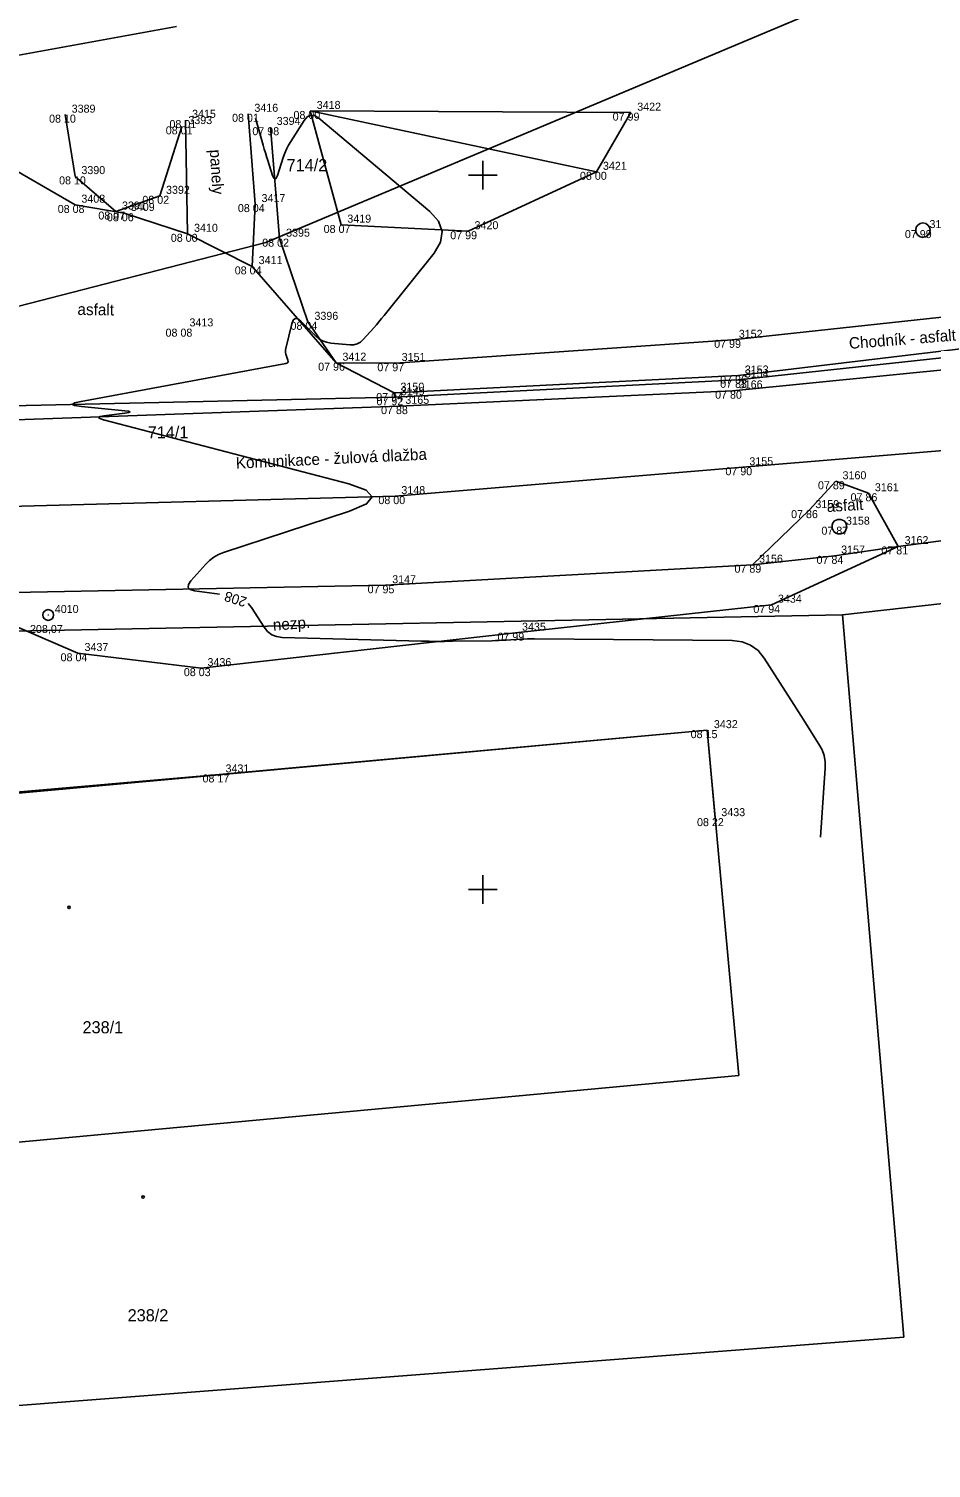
# Model space of a CAD drawing. Extents: x -703403 to -701924, y -1022520 to -1021856.
# Drawn here: x -702540.9 to -702509.3, y -1022370.2 to -1022319.9 of the extents above; entities that cross this region are included whole.
import ezdxf

# ---------------------------------------------------------------- set-up
doc = ezdxf.new("R2010")
doc.units = 0
for name, color, linetype in [('Ex_Contour Labels', 7, 'Continuous'), ('Ex_Major Contours', 7, 'Continuous'), ('Z_bodove_pole', 7, 'Continuous'), ('Z_bodove_pole_cisla', 7, 'Continuous'), ('Z_bodove_pole_vysky', 7, 'Continuous'), ('Z_body', 7, 'Continuous'), ('Z_body_cisla', 7, 'Continuous'), ('Z_body_vysky_redukovane', 7, 'Continuous'), ('Z_budova', 7, 'Continuous'), ('Z_cesta', 7, 'Continuous'), ('Z_chodnik', 7, 'Continuous'), ('Z_hektometricka_sit', 7, 'Continuous'), ('Z_katastr_cisla_pozemkova', 7, 'Continuous'), ('Z_katastr_cisla_stavebni', 7, 'Continuous'), ('Z_katastr_hranice', 7, 'Continuous'), ('Z_katastr_znacky_budov', 7, 'Continuous'), ('Z_komunikace', 7, 'Continuous'), ('Z_komunikace_osa', 7, 'Continuous'), ('Z_obruba', 7, 'Continuous'), ('Z_popisy', 7, 'Continuous'), ('Z_rozhranni', 7, 'Continuous'), ('Z_site_kanalizace_znaky', 7, 'Continuous'), ('Z_zelen_jednotliva', 7, 'Continuous'), ('Z_zelen_obvod', 7, 'Continuous')]:
    doc.layers.add(name, color=color, linetype=linetype)

# ---------------------------------------------------------------- blocks, each defined once
blk = doc.blocks.new('POINT_DISPLAY')
blk.add_line((0, 0), (0, 0))
blk = doc.blocks.new('Z10001')
blk.add_circle((0, 0), 0.25)
blk = doc.blocks.new('Z620')
for p, q in [((-0.25, 0.05), (-0.23, 0.13)), ((-0.25, -0.05), (-0.25, 0.05)), ((-0.23, 0.13), (-0.17, 0.2)), ((-0.17, 0.2), (-0.05, 0.25)), ((-0.05, 0.25), (0.05, 0.25)), ((0.05, 0.25), (0.17, 0.2)), ((0.17, 0.2), (0.23, 0.13)), ((0.23, 0.13), (0.25, 0.05)), ((0.25, 0.05), (0.25, -0.05)), ((-0.2, -0.17), (-0.25, -0.05)), ((-0.13, -0.23), (-0.2, -0.17)), ((-0.05, -0.25), (-0.13, -0.23)), ((0.05, -0.25), (-0.05, -0.25)), ((0.13, -0.23), (0.05, -0.25)), ((0.2, -0.17), (0.13, -0.23)), ((0.25, -0.05), (0.2, -0.17))]:
    blk.add_line(p, q)
blk = doc.blocks.new('Z101')
for radius in [0.188, 0.0025]:
    blk.add_circle((0, 0), radius)

msp = doc.modelspace()

# ---------------------------------------------------------------- linework, layer by layer
at = {"layer": 'Ex_Major Contours'}
for points in [[(-702531.04, -1022322.75), (-702521.02, -1022324.88)], [(-702534.21, -1022339.66), (-702535.084, -1022339.539), (-702535.236, -1022339.498), (-702535.307, -1022339.427), (-702535.299, -1022339.327), (-702535.21, -1022339.197), (-702534.693, -1022338.617), (-702534.557, -1022338.482), (-702534.407, -1022338.369), (-702534.243, -1022338.277), (-702534.066, -1022338.205), (-702529.661, -1022336.754), (-702529.066, -1022336.498), (-702528.873, -1022336.255), (-702529.081, -1022336.024), (-702529.691, -1022335.805), (-702538.261, -1022333.56), (-702538.394, -1022333.516), (-702538.437, -1022333.478), (-702538.389, -1022333.446), (-702538.252, -1022333.42), (-702537.523, -1022333.326), (-702537.386, -1022333.303), (-702537.341, -1022333.281), (-702537.387, -1022333.261), (-702537.524, -1022333.243), (-702539.041, -1022333.094), (-702539.277, -1022333.059), (-702539.356, -1022333.018), (-702539.28, -1022332.971), (-702539.048, -1022332.917), (-702531.895, -1022331.589), (-702531.851, -1022331.575), (-702531.824, -1022331.549), (-702531.814, -1022331.514), (-702531.822, -1022331.468), (-702531.885, -1022331.265), (-702531.897, -1022331.214), (-702531.902, -1022331.163), (-702531.9, -1022331.112), (-702531.891, -1022331.06), (-702531.679, -1022330.197), (-702531.63, -1022330.071), (-702531.561, -1022330.014), (-702531.473, -1022330.027), (-702531.365, -1022330.109), (-702530.848, -1022330.623), (-702530.731, -1022330.722), (-702530.602, -1022330.797), (-702530.463, -1022330.847), (-702530.312, -1022330.873), (-702529.649, -1022330.933), (-702529.516, -1022330.931), (-702529.394, -1022330.9), (-702529.284, -1022330.84), (-702529.186, -1022330.751), (-702528.815, -1022330.336), (-702528.723, -1022330.231), (-702528.633, -1022330.126), (-702528.544, -1022330.019), (-702528.456, -1022329.911), (-702526.707, -1022327.731), (-702526.476, -1022327.341), (-702526.422, -1022326.967), (-702526.547, -1022326.612), (-702526.85, -1022326.273), (-702530.739, -1022323.003), (-702530.884, -1022322.913), (-702531.017, -1022322.896), (-702531.139, -1022322.953), (-702531.25, -1022323.083), (-702531.714, -1022323.815), (-702531.793, -1022323.95), (-702531.864, -1022324.088), (-702531.925, -1022324.231), (-702531.978, -1022324.378), (-702532.184, -1022325.007), (-702532.227, -1022325.106), (-702532.27, -1022325.138), (-702532.312, -1022325.105), (-702532.354, -1022325.007), (-702532.523, -1022324.48), (-702532.564, -1022324.348), (-702532.604, -1022324.216), (-702532.644, -1022324.084), (-702532.682, -1022323.951), (-702532.95, -1022323.007)], [(-702513.187, -1022348.164), (-702513.029, -1022345.753), (-702513.031, -1022345.529), (-702513.068, -1022345.313), (-702513.139, -1022345.106), (-702513.244, -1022344.908), (-702513.734, -1022344.134), (-702513.857, -1022343.94), (-702513.98, -1022343.747), (-702514.103, -1022343.554), (-702514.226, -1022343.361), (-702515.157, -1022341.905), (-702515.375, -1022341.636), (-702515.634, -1022341.443), (-702515.935, -1022341.326), (-702516.279, -1022341.285), (-702523.191, -1022341.225), (-702523.316, -1022341.225), (-702523.441, -1022341.228), (-702523.565, -1022341.232), (-702523.689, -1022341.239), (-702524.187, -1022341.27), (-702524.311, -1022341.277), (-702524.436, -1022341.283), (-702524.56, -1022341.287), (-702524.685, -1022341.29), (-702526.065, -1022341.311), (-702526.336, -1022341.314), (-702526.607, -1022341.314), (-702526.879, -1022341.311), (-702527.15, -1022341.305), (-702532.022, -1022341.174), (-702532.215, -1022341.147), (-702532.384, -1022341.079), (-702532.53, -1022340.969), (-702532.653, -1022340.818), (-702533.095, -1022340.128), (-702533.21, -1022339.983)]]:
    msp.add_lwpolyline(points, dxfattribs=at)
at = {"layer": 'Z_budova'}
for p, q in [((-702534.22, -1022345.97), (-702517.15, -1022344.42)), ((-702517.15, -1022344.42), (-702516.88, -1022347.5)), ((-702547.33, -1022347.12), (-702534.22, -1022345.97))]:
    msp.add_line(p, q, dxfattribs=at)
at = {"layer": 'Z_cesta'}
for p, q in [((-702539.61, -1022322.88), (-702539.26, -1022325.04)), ((-702536.3, -1022325.72), (-702535.53, -1022323.29)), ((-702532.43, -1022323.32), (-702532.11, -1022327.22)), ((-702539.26, -1022325.04), (-702537.84, -1022326.27)), ((-702537.84, -1022326.27), (-702536.3, -1022325.72)), ((-702532.11, -1022327.22), (-702531.12, -1022330.13)), ((-702531.12, -1022330.13), (-702530.13, -1022331.56))]:
    msp.add_line(p, q, dxfattribs=at)
at = {"layer": 'Z_chodnik'}
for p, q in [((-702516.28, -1022330.76), (-702504.25, -1022329.46)), ((-702528.06, -1022331.58), (-702516.28, -1022330.76)), ((-702528.06, -1022331.58), (-702530.13, -1022331.56))]:
    msp.add_line(p, q, dxfattribs=at)
at = {"layer": 'Z_hektometricka_sit'}
for p, q in [((-702525, -1022324.5), (-702525, -1022325.5)), ((-702525.5, -1022325), (-702524.5, -1022325)), ((-702525, -1022349.5), (-702525, -1022350.5)), ((-702525.5, -1022350), (-702524.5, -1022350))]:
    msp.add_line(p, q, dxfattribs=at)
at = {"layer": 'Z_katastr_hranice'}
for p, q in [((-702509.32, -1022317.56), (-702532.59, -1022327.36)), ((-702544.68, -1022321.42), (-702535.71, -1022319.8)), ((-702532.59, -1022327.36), (-702542.68, -1022329.95)), ((-702461.35, -1022334.53), (-702512.42, -1022340.39)), ((-702512.42, -1022340.39), (-702559.94, -1022341.31)), ((-702510.28, -1022365.66), (-702512.42, -1022340.39)), ((-702517.15, -1022344.42), (-702564.67, -1022348.77)), ((-702516.05, -1022356.51), (-702517.15, -1022344.42)), ((-702563.56, -1022360.91), (-702516.05, -1022356.51)), ((-702569.75, -1022370.25), (-702510.28, -1022365.66))]:
    msp.add_line(p, q, dxfattribs=at)
at = {"layer": 'Z_katastr_znacky_budov'}
for centre in [(-702539.472, -1022350.62), (-702536.882, -1022360.76)]:
    msp.add_circle(centre, 0.0437, dxfattribs=at)
at = {"layer": 'Z_komunikace'}
for p, q in [((-702542.16, -1022324.36), (-702539.26, -1022326.04)), ((-702539.26, -1022326.04), (-702537.54, -1022326.33)), ((-702537.54, -1022326.33), (-702535.33, -1022327.05)), ((-702535.33, -1022327.05), (-702533.07, -1022328.19)), ((-702533.07, -1022328.19), (-702530.13, -1022331.56)), ((-702516.07, -1022332.16), (-702504.15, -1022330.87)), ((-702530.13, -1022331.56), (-702528.1, -1022332.62)), ((-702528.09, -1022332.77), (-702516.07, -1022332.16)), ((-702528.09, -1022332.77), (-702544.01, -1022333.13)), ((-702510.48, -1022337.99), (-702504.07, -1022337.14)), ((-702515.57, -1022338.63), (-702512.7, -1022338.32)), ((-702512.7, -1022338.32), (-702510.48, -1022337.99)), ((-702528.4, -1022339.35), (-702515.57, -1022338.63)), ((-702543.95, -1022339.65), (-702528.4, -1022339.35))]:
    msp.add_line(p, q, dxfattribs=at)
at = {"layer": 'Z_komunikace_osa'}
for p, q in [((-702515.91, -1022335.22), (-702503.96, -1022334.23)), ((-702528.07, -1022336.23), (-702515.91, -1022335.22)), ((-702551.96, -1022336.87), (-702528.07, -1022336.23))]:
    msp.add_line(p, q, dxfattribs=at)
at = {"layer": 'Z_obruba'}
for p, q in [((-702516.07, -1022332.01), (-702504.2, -1022330.59)), ((-702528.1, -1022332.62), (-702516.07, -1022332.01)), ((-702528.1, -1022332.62), (-702528.09, -1022332.77))]:
    msp.add_line(p, q, dxfattribs=at)
at = {"layer": 'Z_rozhranni'}
for p, q in [((-702535.4, -1022323.07), (-702535.33, -1022327.05)), ((-702533.21, -1022322.85), (-702532.96, -1022326.01)), ((-702532.96, -1022326.01), (-702533.07, -1022328.19)), ((-702516.27, -1022332.54), (-702504.24, -1022331.34)), ((-702527.93, -1022333.08), (-702516.27, -1022332.54)), ((-702543.96, -1022333.66), (-702527.93, -1022333.08)), ((-702513.59, -1022336.72), (-702512.65, -1022335.71)), ((-702512.65, -1022335.71), (-702511.51, -1022336.13)), ((-702510.48, -1022337.99), (-702511.51, -1022336.13)), ((-702513.59, -1022336.72), (-702515.57, -1022338.63)), ((-702514.91, -1022340.04), (-702510.48, -1022337.99)), ((-702539.16, -1022341.73), (-702543.95, -1022339.65)), ((-702514.91, -1022340.04), (-702523.86, -1022341.01)), ((-702523.86, -1022341.01), (-702534.85, -1022342.25)), ((-702534.85, -1022342.25), (-702539.16, -1022341.73))]:
    msp.add_line(p, q, dxfattribs=at)
at = {"layer": 'Z_zelen_obvod'}
for p, q in [((-702531.04, -1022322.75), (-702529.96, -1022326.74)), ((-702531.04, -1022322.75), (-702519.83, -1022322.81)), ((-702521.02, -1022324.88), (-702519.83, -1022322.81)), ((-702525.51, -1022326.96), (-702521.02, -1022324.88)), ((-702529.96, -1022326.74), (-702525.51, -1022326.96))]:
    msp.add_line(p, q, dxfattribs=at)

# ---------------------------------------------------------------- block references
at = {"layer": 'Z_bodove_pole'}
msp.add_blockref('Z101', (-702540.2, -1022340.39), dxfattribs=at)
at = {"layer": 'Z_body'}
for p in [(-702531.04, -1022322.75), (-702519.83, -1022322.81), (-702539.61, -1022322.88), (-702535.53, -1022323.29), (-702535.4, -1022323.07), (-702533.21, -1022322.85), (-702532.43, -1022323.32), (-702539.26, -1022325.04), (-702521.02, -1022324.88), (-702536.3, -1022325.72), (-702539.26, -1022326.04), (-702537.84, -1022326.27), (-702537.54, -1022326.33), (-702532.96, -1022326.01), (-702529.96, -1022326.74), (-702535.33, -1022327.05), (-702532.11, -1022327.22), (-702525.51, -1022326.96), (-702509.61, -1022326.92), (-702533.07, -1022328.19), (-702535.49, -1022330.37), (-702531.12, -1022330.13), (-702516.28, -1022330.76), (-702530.13, -1022331.56), (-702528.06, -1022331.58), (-702516.07, -1022332.01), (-702516.07, -1022332.16), (-702528.1, -1022332.62), (-702528.09, -1022332.77), (-702516.27, -1022332.54), (-702527.93, -1022333.08), (-702515.91, -1022335.22), (-702512.65, -1022335.71), (-702528.07, -1022336.23), (-702511.51, -1022336.13), (-702513.59, -1022336.72), (-702512.53, -1022337.3), (-702512.7, -1022338.32), (-702510.48, -1022337.99), (-702515.57, -1022338.63), (-702528.4, -1022339.35), (-702540.2, -1022340.39), (-702514.91, -1022340.04), (-702523.86, -1022341.01), (-702539.16, -1022341.73), (-702534.85, -1022342.25), (-702517.15, -1022344.42), (-702534.22, -1022345.97), (-702516.88, -1022347.5)]:
    msp.add_blockref('POINT_DISPLAY', p, dxfattribs=at)
at = {"layer": 'Z_site_kanalizace_znaky'}
msp.add_blockref('Z620', (-702512.53, -1022337.3), dxfattribs=at)
at = {"layer": 'Z_zelen_jednotliva'}
msp.add_blockref('Z10001', (-702509.61, -1022326.92), dxfattribs=at)

# ---------------------------------------------------------------- texts
at = {"layer": 'Ex_Contour Labels'}
msp.add_text('208', height=0.35, rotation=162.2988, dxfattribs=at).set_placement((-702533.225, -1022339.789))
at = {"layer": 'Z_bodove_pole_cisla'}
msp.add_text('4010', height=0.28, dxfattribs=at).set_placement((-702539.97, -1022340.32))
at = {"layer": 'Z_bodove_pole_vysky'}
msp.add_text('208,07', height=0.28, dxfattribs=at).set_placement((-702540.837, -1022341.02))
at = {"layer": 'Z_body_cisla'}
for s, p in [('3389', (-702539.38, -1022322.81)), ('3415', (-702535.17, -1022322.99)), ('3416', (-702532.99, -1022322.78)), ('3418', (-702530.81, -1022322.68)), ('3422', (-702519.6, -1022322.74)), ('3393', (-702535.3, -1022323.21)), ('3394', (-702532.21, -1022323.24)), ('3390', (-702539.04, -1022324.96)), ('3421', (-702520.8, -1022324.81)), ('3408', (-702539.04, -1022325.96)), ('3392', (-702536.08, -1022325.65)), ('3417', (-702532.74, -1022325.94)), ('3391', (-702537.62, -1022326.2)), ('3409', (-702537.31, -1022326.25)), ('3410', (-702535.1, -1022326.98)), ('3395', (-702531.88, -1022327.15)), ('3419', (-702529.74, -1022326.66)), ('3420', (-702525.29, -1022326.89)), ('3171', (-702509.38, -1022326.85)), ('3411', (-702532.84, -1022328.11)), ('3396', (-702530.89, -1022330.06)), ('3413', (-702535.26, -1022330.29)), ('3152', (-702516.05, -1022330.69)), ('3412', (-702529.91, -1022331.49)), ('3151', (-702527.84, -1022331.5)), ('3153', (-702515.84, -1022331.94)), ('3154', (-702515.84, -1022332.08)), ('3150', (-702527.88, -1022332.54)), ('3166', (-702516.05, -1022332.46)), ('3149', (-702527.87, -1022332.7)), ('3165', (-702527.71, -1022333)), ('3155', (-702515.68, -1022335.15)), ('3160', (-702512.42, -1022335.64)), ('3148', (-702527.85, -1022336.16)), ('3161', (-702511.29, -1022336.06)), ('3159', (-702513.37, -1022336.65)), ('3158', (-702512.3, -1022337.23)), ('3157', (-702512.47, -1022338.24)), ('3162', (-702510.25, -1022337.91)), ('3156', (-702515.34, -1022338.56)), ('3147', (-702528.17, -1022339.28)), ('3434', (-702514.68, -1022339.96)), ('3435', (-702523.63, -1022340.94)), ('3437', (-702538.93, -1022341.65)), ('3436', (-702534.63, -1022342.18)), ('3432', (-702516.92, -1022344.35)), ('3431', (-702534, -1022345.9)), ('3433', (-702516.66, -1022347.43))]:
    msp.add_text(s, height=0.28, dxfattribs=at).set_placement(p)
at = {"layer": 'Z_body_vysky_redukovane'}
for s, p in [('08 00', (-702531.623, -1022323.03)), ('07 99', (-702520.46, -1022323.09)), ('08 10', (-702540.17, -1022323.16)), ('08 01', (-702536.09, -1022323.57)), ('08 01', (-702535.96, -1022323.35)), ('08 01', (-702533.77, -1022323.13)), ('07 98', (-702533.06, -1022323.6)), ('08 10', (-702539.82, -1022325.32)), ('08 00', (-702521.603, -1022325.16)), ('08 02', (-702536.907, -1022326)), ('08 08', (-702539.867, -1022326.32)), ('08 07', (-702538.447, -1022326.55)), ('08 06', (-702538.147, -1022326.61)), ('08 04', (-702533.567, -1022326.29)), ('08 07', (-702530.567, -1022327.02)), ('08 00', (-702535.913, -1022327.33)), ('08 02', (-702532.717, -1022327.5)), ('07 99', (-702526.14, -1022327.24)), ('07 99', (-702510.24, -1022327.2)), ('08 04', (-702533.677, -1022328.47)), ('08 08', (-702536.097, -1022330.65)), ('08 04', (-702531.727, -1022330.41)), ('07 99', (-702516.91, -1022331.04)), ('07 96', (-702530.76, -1022331.84)), ('07 97', (-702528.69, -1022331.86)), ('07 96', (-702516.7, -1022332.29)), ('07 83', (-702516.7, -1022332.44)), ('07 94', (-702528.73, -1022332.9)), ('07 92', (-702528.72, -1022333.05)), ('07 80', (-702516.877, -1022332.82)), ('07 88', (-702528.56, -1022333.36)), ('07 90', (-702516.517, -1022335.5)), ('07 89', (-702513.28, -1022335.99)), ('08 00', (-702528.653, -1022336.51)), ('07 86', (-702512.14, -1022336.41)), ('07 86', (-702514.22, -1022337)), ('07 87', (-702513.16, -1022337.58)), ('07 84', (-702513.33, -1022338.6)), ('07 81', (-702511.063, -1022338.27)), ('07 89', (-702516.2, -1022338.91)), ('07 95', (-702529.03, -1022339.63)), ('07 94', (-702515.54, -1022340.32)), ('07 99', (-702524.49, -1022341.29)), ('08 04', (-702539.767, -1022342.01)), ('08 03', (-702535.457, -1022342.53)), ('08 15', (-702517.733, -1022344.7)), ('08 17', (-702534.803, -1022346.25)), ('08 22', (-702517.51, -1022347.78))]:
    msp.add_text(s, height=0.28, dxfattribs=at).set_placement(p)
at = {"layer": 'Z_katastr_cisla_pozemkova'}
for s, p in [('714/2', (-702531.864, -1022324.86)), ('714/1', (-702536.72, -1022334.21))]:
    msp.add_text(s, height=0.425, dxfattribs=at).set_placement(p)
at = {"layer": 'Z_katastr_cisla_stavebni'}
for s, p in [('238/1', (-702538.999, -1022355.03)), ('238/2', (-702537.422, -1022365.11))]:
    msp.add_text(s, height=0.425, dxfattribs=at).set_placement(p)
at = {"layer": 'Z_popisy'}
for s, rotation, p in [('panely', 273.6, (-702534.55, -1022324.11)), ('asfalt', 359.1, (-702539.18, -1022329.89)), ('Chodník - asfalt', 4.5, (-702512.18, -1022331.08)), ('Komunikace - žulová dlažba', 2.7, (-702533.63, -1022335.27)), ('asfalt', 3.6, (-702512.96, -1022336.79)), ('nezp.', 4.5, (-702532.33, -1022340.94))]:
    msp.add_text(s, height=0.4, rotation=rotation, dxfattribs=at).set_placement(p)

doc.saveas('drawing.dxf')
